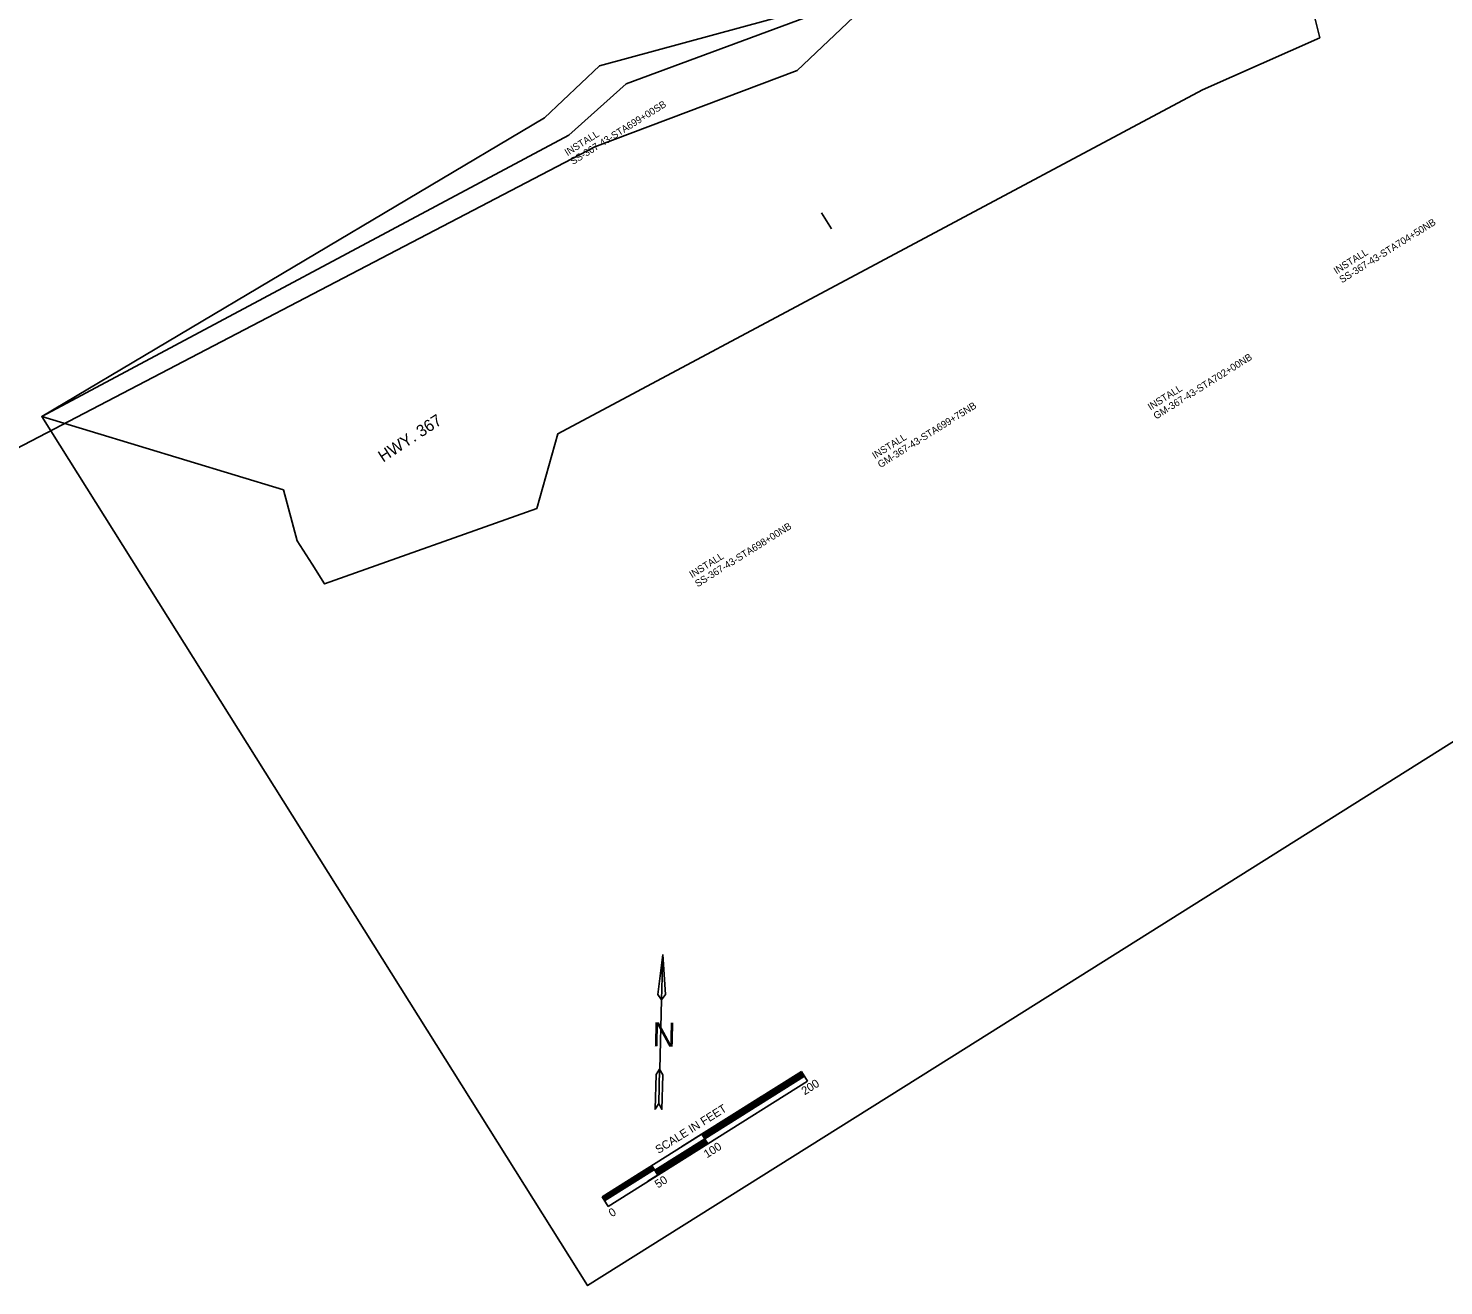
# Model space of a CAD drawing. Extents: x 1289840 to 1295361, y 220865 to 226414.
# Drawn here: x 1292500 to 1293702, y 222123 to 223191 of the extents above; entities that cross this region are included whole.
import ezdxf

# ---------------------------------------------------------------- set-up
doc = ezdxf.new("R2010")
doc.units = 0
for name, color, linetype in [('level 1050', 7, 'Continuous'), ('Plan Text', 7, 'Continuous'), ('R_Horz Alg Stationing_Side Road', 7, 'Continuous'), ('R_No Plot', 7, 'Continuous'), ('SIGN CALLOUTS', 7, 'Continuous'), ('SIGN STRUC', 7, 'Continuous')]:
    doc.layers.add(name, color=color, linetype=linetype)

msp = doc.modelspace()

# ---------------------------------------------------------------- linework, layer by layer
msp.add_lwpolyline([(1292980.7, 223090.1), (1292443.5, 222809.8), (1291900.1, 223383.1), (1292988.8, 224414.9), (1293451.5, 223926.8), (1293499.2, 223784), (1293629.8, 223673.9), (1293562.5, 223543.2), (1293152.7, 223154.8)], close=True)
at = {"layer": 'Plan Text'}
for p, q in [((1293038.5, 222404.4), (1293034.4, 222370.4)), ((1293034.4, 222370.4), (1293037.4, 222365.9)), ((1293035.9, 222307), (1293037.4, 222365.9))]:
    msp.add_line(p, q, dxfattribs=at)
for points in [[(1293038.4, 222404.2), (1293037.4, 222365.9), (1293040.7, 222370.3)], [(1293032.8, 222302.5), (1293032, 222273), (1293035.1, 222277.8), (1293035.8, 222307.1)], [(1293035.8, 222307.1), (1293038.6, 222302.3), (1293037.8, 222272.8), (1293035.1, 222277.8)]]:
    msp.add_lwpolyline(points, close=True, dxfattribs=at)
at = {"layer": 'R_Horz Alg Stationing_Side Road'}
msp.add_line((1293173.3, 223033.9), (1293181.9, 223020.4), dxfattribs=at)
at = {"layer": 'R_No Plot'}
msp.add_line((1292984.7, 223158.8), (1293225.6, 223224.4), dxfattribs=at)
msp.add_lwpolyline([(1293643.9, 222543.7), (1294313.2, 222964.3), (1294052.1, 223379.8), (1294028.2, 223364.9), (1293848.7, 223650.5), (1293742.6, 223744.2), (1293628.8, 223642.2), (1293608.7, 223658), (1293487.3, 223516.6), (1293526.8, 223482.6), (1293449.8, 223393.5), (1293356.6, 223360), (1293225.6, 223224.4), (1293007.4, 223143.4), (1292958.6, 223100), (1292510.9, 222861.1), (1292974.6, 222123.2), (1293296.1, 222325.2)], close=True, dxfattribs=at)
for points in [[(1293589.5, 223210.9), (1293596.5, 223182.6), (1293497, 223138.3), (1292949.3, 222846.5), (1292931.4, 222783), (1292751.2, 222718.9), (1292740.7, 222735.8), (1292728, 222755.6), (1292716.2, 222798.7), (1292510.9, 222861.1)], [(1292510.9, 222861.1), (1292938, 223114.6), (1292984.7, 223158.8)]]:
    msp.add_lwpolyline(points, dxfattribs=at)
at = {"layer": 'SIGN CALLOUTS'}
for p, q in [((1293054.7, 222241.2), (1293156.3, 222305)), ((1293072, 222251.1), (1293156.7, 222304.4)), ((1293072.5, 222250.5), (1293157.1, 222303.7)), ((1293072.9, 222249.8), (1293157.6, 222303)), ((1293073.3, 222249.1), (1293158, 222302.3)), ((1293073.7, 222248.4), (1293158.4, 222301.6)), ((1293074.2, 222247.8), (1293158.8, 222301)), ((1293161.4, 222296.9), (1293156.3, 222305)), ((1292992.1, 222190.5), (1293161.4, 222296.9)), ((1292986.9, 222198.6), (1293122.4, 222283.7)), ((1293074.2, 222247.8), (1293125, 222279.7)), ((1293031.8, 222221.2), (1293074.2, 222247.8)), ((1293032.3, 222220.5), (1293074.6, 222247.1)), ((1293032.7, 222219.8), (1293075, 222246.4)), ((1293033.1, 222219.1), (1293075.5, 222245.7)), ((1293033.5, 222218.4), (1293075.9, 222245.1)), ((1293034, 222217.8), (1293076.3, 222244.4)), ((1293076.7, 222243.7), (1293071.6, 222251.8)), ((1293025.9, 222211.8), (1293059.8, 222233.1)), ((1292986.9, 222198.6), (1293020.8, 222219.9)), ((1292987.4, 222197.9), (1293029.7, 222224.5)), ((1292987.8, 222197.3), (1293030.1, 222223.9)), ((1292988.2, 222196.6), (1293030.6, 222223.2)), ((1292988.6, 222195.9), (1293031, 222222.5)), ((1292989.1, 222195.2), (1293031.4, 222221.8)), ((1293034.4, 222217.1), (1293029.3, 222225.2)), ((1292992.1, 222190.5), (1292986.9, 222198.6))]:
    msp.add_line(p, q, dxfattribs=at)

# ---------------------------------------------------------------- texts
at = {"layer": 'level 1050'}
for s, p in [('SS-367-43-STA699+00SB', (1292962.2, 223074.5)), ('INSTALL', (1292957.5, 223082.1)), ('SS-367-43-STA704+50NB', (1293615.5, 222974.1)), ('INSTALL', (1293610.7, 222981.7)), ('GM-367-43-STA702+00NB', (1293457.6, 222858.4)), ('INSTALL', (1293452.8, 222866.1)), ('GM-367-43-STA699+75NB', (1293223.4, 222817.2)), ('INSTALL', (1293218.7, 222824.8)), ('SS-367-43-STA698+00NB', (1293068.2, 222716)), ('INSTALL', (1293063.4, 222723.7))]:
    msp.add_text(s, height=6, rotation=32.1185, dxfattribs=at).set_placement(p)
at = {"layer": 'Plan Text'}
msp.add_text('N', height=20.4, rotation=358.4728, dxfattribs=at).set_placement((1293029.5, 222326.5))
at = {"layer": 'SIGN CALLOUTS'}
for s, height, p in [('200', 7, (1293159, 222284.7)), ('SCALE IN FEET', 7.001, (1293034.9, 222234.9)), ('100', 7, (1293076, 222231.2)), ('50', 7, (1293034.4, 222205.6)), ('0', 7, (1292995.2, 222181.1))]:
    msp.add_text(s, height=height, rotation=32.1437, dxfattribs=at).set_placement(p)
at = {"layer": 'SIGN STRUC'}
msp.add_text('HWY. 367', height=10, rotation=33.2255, dxfattribs=at).set_placement((1292800.9, 222821.9))

doc.saveas('drawing.dxf')
